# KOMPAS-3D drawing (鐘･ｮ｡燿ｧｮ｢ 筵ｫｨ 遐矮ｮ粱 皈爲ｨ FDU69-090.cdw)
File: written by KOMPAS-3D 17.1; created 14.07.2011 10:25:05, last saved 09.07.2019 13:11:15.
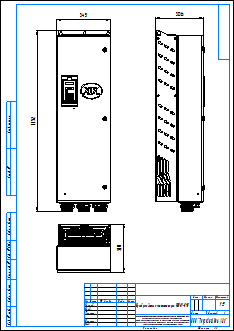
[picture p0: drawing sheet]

Title block, sheet 1: name: Преобразователи частоты серии FDU69-090; scale: 1:5; sheets: 1; sheet format: A3; stored path: \\adlc.lan\data\АДЛ_ПКД\3D-модели\Поставщики\Оборудование Emotron\Преобразователи частоты\Серия FDU 2.0\KOMPAS 2D\Преобразователи частоты серии FDU69-090.cdw

Views: Спереди 1
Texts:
  Рама для чертежей
  Лит-Масса-Масштаб
  Материал-Предприятие
  Масштаб
  Изм.
  Лист
  № докум.
  Подп.
  Дата
  Лит.
  Разраб.
  Пров.
  Т.контр.
  Листов
  Внимание! Данный продукт является объектом авторского права ООО «Торговый Дом АДЛ».
  Запрещается изменение, копирование, распространение
  (в том числе путем копирования на другие сайты и ресурсы в Интернете)
  или любое иное использование информации и объектов без предварительного
  согласия правообладателя (ООО «Торговый Дом АДЛ»).
  Н.контр.
  Утв.
  ООО "Торговый дом АДЛ"
  Изменение
  Номер документа
  Подпись
  Обозначение документа
  Наименование изделия
  Масса изделия по ГОСТ 2.109-73
  Порядковый номер листа
  Общее количество листов в документе
  Характер работы, выполненной лицом, подписавшим документ
  Наименование или индекс предприятия, выпускающего документ
  Инв. № подл.
  Подп. и дата
  Взам. инв. №
  Инв. № дубл.
  Инвентарный номер подлинника по ГОСТ 2.501-68
  Подпись принявшего подлинник в отдел технической документации
  Инвентарный номер подлинника, взамен которого выпущен данный подлинник
  Инвентарный номер дубликата по ГОСТ 2.502-68
  Подпись принявшего дубликат в отдел технической документации
  Справ. №
  Перв. примен.
  Обозначение документа, взамен или на основании которого выпущен данный документ
  Обозначение документа, в котором впервые записан данный документ
  Подпись лица, копировавшего чертеж
  Обозначение формата листа
  !Рама для чертежа
Dimensions and other numbers on the sheet: 345; 1152; 306; 310; 1:5; 1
